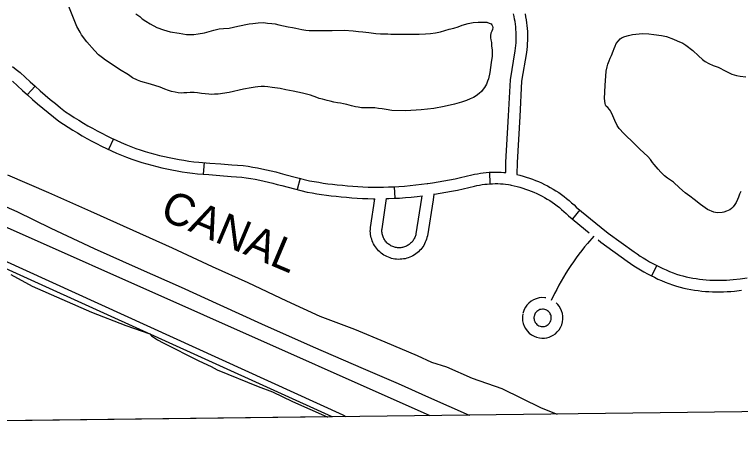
# Model space of a CAD drawing. Extents: x 3704301 to 3742427, y 506229 to 532009.
# Drawn here: x 3717011 to 3718892, y 511646 to 512803 of the extents above; entities that cross this region are included whole.
import ezdxf

# ---------------------------------------------------------------- set-up
doc = ezdxf.new("R2010")
doc.units = 0
for name, color, linetype in [('V-GRID-FRAM', 7, 'Continuous'), ('V-LEVE-TOET', 7, 'Continuous'), ('V-RIVR-IDEN', 7, 'Continuous'), ('V-ROAD-CNTR', 7, 'Continuous'), ('V-SITE-VEGE', 7, 'Continuous'), ('V-TOPO-BNDY', 7, 'Continuous'), ('V-TOPO-SHOR', 7, 'Continuous')]:
    doc.layers.add(name, color=color, linetype=linetype)

msp = doc.modelspace()

# ---------------------------------------------------------------- linework, layer by layer
at = {"layer": 'V-GRID-FRAM'}
msp.add_lwpolyline([(3708355.7, 529827.8), (3740022.4, 530214.7), (3740252.5, 512033.3), (3708569.9, 511646.2), (3708355.7, 529827.8)], dxfattribs=at)
at = {"layer": 'V-LEVE-TOET'}
for points in [[(3715612.8, 512669.7), (3716188.4, 512588.5), (3716253.4, 512575), (3716326.9, 512545.9), (3718086.8, 511762.5)], [(3717870.2, 511759.8), (3717862.2, 511763.5), (3716347.2, 512454.4), (3716290.4, 512479.5), (3716249.5, 512494.5), (3716192.9, 512507.2), (3715594.6, 512592.7)]]:
    msp.add_lwpolyline(points, dxfattribs=at)
at = {"layer": 'V-ROAD-CNTR'}
for p, q in [((3717063.9, 512616.6), (3717043.8, 512594.3)), ((3717266.8, 512480.2), (3717254.1, 512453)), ((3717502.1, 512418.5), (3717499.7, 512388.6)), ((3718241, 512393.6), (3718242.5, 512363.6)), ((3717750.5, 512378), (3717743.2, 512348.9)), ((3717994.2, 512356), (3717995.8, 512326)), ((3718475, 512296), (3718456, 512272.8)), ((3718674.5, 512151.8), (3718661.1, 512124.9))]:
    msp.add_line(p, q, dxfattribs=at)
for points in [[(3718283.3, 512392.8), (3718284.1, 512420.2), (3718291, 512539.7), (3718295.6, 512633.4), (3718308, 512708.8), (3718309, 512715.7), (3718309.7, 512722.5), (3718310.2, 512729.4), (3718310.6, 512736.2), (3718310.8, 512743.1), (3718310.7, 512750), (3718310.5, 512756.9), (3718310, 512763.7), (3718309.4, 512770.6), (3718308.6, 512777.4), (3718307.6, 512784.2), (3718306.4, 512791), (3718305, 512797.8), (3718303.4, 512804.5)], [(3718313.1, 512387.5), (3718314.1, 512418.9), (3718320.9, 512538.1), (3718325.5, 512630.2), (3718337.7, 512704.3), (3718338.7, 512712), (3718339.6, 512719.7), (3718340.2, 512727.4), (3718340.6, 512735.1), (3718340.8, 512742.9), (3718340.7, 512750.6), (3718340.4, 512758.3), (3718340, 512766.1), (3718339.2, 512773.8), (3718338.3, 512781.4), (3718337.2, 512789.1), (3718335.8, 512796.7), (3718334.2, 512804.3)], [(3717005.2, 512667.8), (3717015.2, 512660.3), (3717025.5, 512652.2), (3717038.6, 512639.8), (3717051.2, 512628.1), (3717064, 512616.5), (3717076.9, 512605.1), (3717090, 512593.8), (3717103.2, 512582.7), (3717116.5, 512571.8), (3717129.9, 512561), (3717143.1, 512550.7), (3717154.2, 512543.2), (3717165.7, 512535.8), (3717177.4, 512528.4), (3717189.1, 512521.3), (3717201, 512514.4), (3717213, 512507.6), (3717225, 512501), (3717237.2, 512494.6), (3717249.5, 512488.5), (3717261.9, 512482.4), (3717274.3, 512476.6), (3717286.9, 512471), (3717299.5, 512465.6), (3717312.2, 512460.4), (3717324.7, 512455.5), (3717336.7, 512451.5), (3717349.1, 512447.7), (3717361.5, 512444), (3717373.9, 512440.6), (3717386.5, 512437.4), (3717399, 512434.4), (3717411.6, 512431.7), (3717424.3, 512429.1), (3717437, 512426.8), (3717449.8, 512424.6), (3717462.5, 512422.7), (3717475.4, 512421), (3717488.1, 512419.6), (3717516.5, 512417.3), (3717545.3, 512415.1), (3717574, 512412.9), (3717603.3, 512410.8), (3717615.8, 512409), (3717627.8, 512407.1), (3717639.9, 512404.9), (3717651.9, 512402.6), (3717663.8, 512400.1), (3717675.7, 512397.3), (3717687.6, 512394.4), (3717699.4, 512391.3), (3717710.8, 512388), (3717775.4, 512371.7), (3717787, 512369.5), (3717799, 512367.5)], [(3717005.9, 512629.4), (3717018.1, 512617.9), (3717031, 512605.9), (3717044, 512594.1), (3717057.2, 512582.5), (3717070.5, 512571), (3717084, 512559.7), (3717097.6, 512548.5), (3717111.3, 512537.5), (3717125.5, 512526.4), (3717137.6, 512518.2), (3717149.6, 512510.5), (3717161.6, 512502.9), (3717173.8, 512495.5), (3717186, 512488.4), (3717198.4, 512481.4), (3717210.9, 512474.6), (3717223.5, 512468), (3717236.2, 512461.6), (3717249, 512455.4), (3717261.8, 512449.3), (3717274.8, 512443.5), (3717287.9, 512437.9), (3717301, 512432.5), (3717314.5, 512427.2), (3717327.6, 512422.9), (3717340.4, 512418.9), (3717353.3, 512415.2), (3717366.3, 512411.6), (3717379.3, 512408.3), (3717392.3, 512405.2), (3717405.5, 512402.3), (3717418.6, 512399.7), (3717431.8, 512397.2), (3717445.1, 512395), (3717458.4, 512393), (3717471.7, 512391.3), (3717485.2, 512389.7), (3717514.2, 512387.4), (3717543, 512385.2), (3717571.8, 512383), (3717600.1, 512380.9), (3717611.3, 512379.3), (3717622.8, 512377.5), (3717634.4, 512375.4), (3717645.9, 512373.2), (3717657.3, 512370.8), (3717668.8, 512368.2), (3717680.1, 512365.3), (3717691.4, 512362.3), (3717703, 512359), (3717769, 512342.4), (3717781.7, 512340), (3717794, 512337.9)], [(3717798.8, 512367.5), (3717810.8, 512365.6), (3717822.8, 512364), (3717834.8, 512362.6), (3717847, 512361.4), (3717860.5, 512359.9), (3717873.7, 512358.5), (3717886.9, 512357.4), (3717900.2, 512356.5), (3717913.5, 512355.8), (3717926.8, 512355.3), (3717940.1, 512355), (3717953.4, 512354.9), (3717961.2, 512355), (3717966.7, 512355.1), (3717979.9, 512355.4), (3717993.2, 512355.9), (3718006.5, 512356.7), (3718021.1, 512357.8), (3718035.7, 512359.1), (3718050.3, 512360.6), (3718065, 512362.4), (3718079.5, 512364.3), (3718081.2, 512364.5), (3718094.1, 512366.4), (3718108.6, 512368.7), (3718123.1, 512371.3), (3718137.6, 512374), (3718152, 512376.9), (3718166.4, 512380), (3718180.7, 512383.3), (3718195.3, 512386.8), (3718202.7, 512388.5), (3718210.2, 512389.9), (3718217.7, 512391.2), (3718225.3, 512392.2), (3718232.9, 512393), (3718240.6, 512393.6), (3718248.2, 512394), (3718255.9, 512394.1), (3718263.5, 512394.1), (3718271.2, 512393.8), (3718278.8, 512393.3), (3718283.5, 512392.8)], [(3718312.5, 512387.7), (3718320.3, 512385.8), (3718328.5, 512383.6), (3718336.7, 512381.2), (3718344.7, 512378.5), (3718352.7, 512375.7), (3718360.7, 512372.6), (3718368.5, 512369.3), (3718376.3, 512365.8), (3718383.9, 512362.1), (3718391.5, 512358.2), (3718398.9, 512354.1), (3718406.3, 512349.8), (3718413.5, 512345.3), (3718420.6, 512340.7), (3718427.6, 512335.8), (3718434.4, 512330.7), (3718441.1, 512325.5), (3718447.7, 512320.1), (3718454.1, 512314.5), (3718460.4, 512308.8), (3718465.9, 512303.5), (3718530.8, 512250.4), (3718548.4, 512236), (3718615.8, 512187.3), (3718623.7, 512181.7), (3718631.7, 512176.4), (3718639.7, 512171.3), (3718647.9, 512166.3), (3718656.2, 512161.5), (3718664.6, 512156.9), (3718673.1, 512152.4), (3718681.7, 512148.2), (3718690.3, 512144.1), (3718699.1, 512140.2), (3718707.9, 512136.5), (3718716.8, 512133), (3718725.8, 512129.7), (3718734.5, 512126.7), (3718742.6, 512124.6), (3718751.1, 512122.5), (3718759.7, 512120.7), (3718768.3, 512119.1), (3718776.9, 512117.7), (3718785.6, 512116.5), (3718794.3, 512115.4), (3718803, 512114.6), (3718811.8, 512114), (3718820.5, 512113.6), (3718829.3, 512113.4), (3718838.1, 512113.4), (3718846.8, 512113.6), (3718855.6, 512114), (3718864.3, 512114.6), (3718873.1, 512115.4), (3718891.1, 512117.4), (3718909, 512119.6)], [(3718096.5, 512336.5), (3718098.6, 512336.8), (3718113.6, 512339.1), (3718128.5, 512341.7), (3718143.3, 512344.5), (3718158.1, 512347.5), (3718172.9, 512350.7), (3718187.7, 512354.1), (3718202.1, 512357.6), (3718208.8, 512359.1), (3718215.5, 512360.4), (3718222.2, 512361.5), (3718228.9, 512362.4), (3718235.7, 512363.1), (3718242.5, 512363.6), (3718249.2, 512364), (3718256, 512364.1), (3718262.8, 512364.1), (3718269.6, 512363.8), (3718276.4, 512363.4), (3718282.9, 512362.7), (3718290.3, 512361.6), (3718295, 512360.7), (3718297.8, 512360.2), (3718305.4, 512358.6), (3718312.9, 512356.8), (3718320.3, 512354.7), (3718327.7, 512352.5), (3718335, 512350.1), (3718342.3, 512347.5), (3718349.5, 512344.8), (3718356.6, 512341.8), (3718363.6, 512338.6), (3718370.5, 512335.3), (3718377.4, 512331.7), (3718384.1, 512328), (3718390.8, 512324.1), (3718397.3, 512320.1), (3718403.8, 512315.8), (3718410.1, 512311.4), (3718416.3, 512306.8), (3718422.4, 512302.1), (3718428.3, 512297.2), (3718434.1, 512292.2), (3718439.8, 512286.9), (3718445.9, 512281), (3718499.9, 512236.9)], [(3717794.2, 512337.8), (3717806.5, 512336), (3717819, 512334.3), (3717831.5, 512332.8), (3717843.8, 512331.6), (3717857.3, 512330), (3717871, 512328.7), (3717884.7, 512327.5), (3717898.4, 512326.6), (3717912.1, 512325.8), (3717925.9, 512325.3), (3717939.6, 512325), (3717944, 512325)], [(3718096.9, 512336.5), (3718095.2, 512322.5), (3718080.3, 512228.6), (3718079.4, 512224.3), (3718078.2, 512220.1), (3718076.8, 512216), (3718075.1, 512211.9), (3718073.2, 512208), (3718071.1, 512204.1), (3718068.7, 512200.4), (3718066.2, 512196.9), (3718063.4, 512193.5), (3718060.4, 512190.3), (3718057.3, 512187.2), (3718053.9, 512184.4), (3718050.4, 512181.7), (3718046.8, 512179.3), (3718043, 512177), (3718039.1, 512175), (3718035.1, 512173.3), (3718031, 512171.8), (3718026.8, 512170.5), (3718022.6, 512169.4), (3718018.3, 512168.7), (3718013.9, 512168.1), (3718009.5, 512167.9), (3718005.2, 512167.8), (3718000.8, 512168.1), (3717996.4, 512168.6), (3717992.1, 512169.3), (3717987.8, 512170.4), (3717983.6, 512171.6), (3717979.5, 512173.1), (3717975.5, 512174.9), (3717971.6, 512176.8), (3717967.8, 512179), (3717964.2, 512181.5), (3717960.6, 512184.1), (3717957.3, 512186.9), (3717954.1, 512189.9), (3717951.1, 512193.2), (3717948.4, 512196.5), (3717945.8, 512200.1), (3717943.4, 512203.7), (3717941.2, 512207.6), (3717939.3, 512211.5), (3717937.6, 512215.5), (3717936.1, 512219.7), (3717934.9, 512223.9), (3717934, 512228.2), (3717933.3, 512232.5), (3717932.8, 512236.8), (3717932.6, 512241.2), (3717932.7, 512245.6), (3717933, 512250.1), (3717944, 512325)], [(3718066.2, 512332.3), (3718065.5, 512326.6), (3718050.8, 512234.1), (3718050.3, 512231.6), (3718049.6, 512229), (3718048.7, 512226.6), (3718047.7, 512224.2), (3718046.6, 512221.8), (3718045.3, 512219.5), (3718043.9, 512217.3), (3718042.4, 512215.2), (3718040.7, 512213.2), (3718038.9, 512211.2), (3718037.1, 512209.4), (3718035.1, 512207.7), (3718033, 512206.1), (3718030.8, 512204.7), (3718028.6, 512203.3), (3718026.2, 512202.1), (3718023.8, 512201.1), (3718021.4, 512200.2), (3718018.9, 512199.4), (3718016.3, 512198.8), (3718013.8, 512198.3), (3718011.2, 512198), (3718008.6, 512197.9), (3718005.9, 512197.8), (3718003.3, 512198), (3718000.7, 512198.3), (3717998.2, 512198.7), (3717995.6, 512199.3), (3717993.1, 512200.1), (3717990.6, 512201), (3717988.2, 512202), (3717985.9, 512203.2), (3717983.6, 512204.5), (3717981.5, 512206), (3717979.4, 512207.5), (3717977.4, 512209.2), (3717975.5, 512211), (3717973.7, 512213), (3717972, 512215), (3717970.5, 512217.1), (3717969.1, 512219.3), (3717967.8, 512221.6), (3717966.6, 512223.9), (3717965.6, 512226.3), (3717964.7, 512228.8), (3717964, 512231.3), (3717963.4, 512233.9), (3717963, 512236.4), (3717962.8, 512239), (3717962.6, 512241.7), (3717962.7, 512244.3), (3717962.9, 512246.8), (3717974.4, 512325.2)], [(3717974.1, 512325.2), (3717980.9, 512325.4), (3717994.7, 512326), (3718008.4, 512326.7), (3718023.6, 512327.9), (3718038.6, 512329.3), (3718053.7, 512330.8), (3718066.5, 512332.3)], [(3718511.4, 512227.5), (3718495.3, 512209.2), (3718487.7, 512199.9), (3718480.2, 512190.5), (3718473, 512181), (3718465.9, 512171.4), (3718458.9, 512161.6), (3718452.2, 512151.7), (3718445.6, 512141.7), (3718439.2, 512131.6), (3718433, 512121.4), (3718426.9, 512111), (3718421.1, 512100.6), (3718415.4, 512090), (3718409.9, 512079.4), (3718400.8, 512060.8)], [(3718522.8, 512218.1), (3718530.1, 512212.2), (3718598.4, 512162.8), (3718606.8, 512157), (3718615.3, 512151.3), (3718623.9, 512145.8), (3718632.6, 512140.5), (3718641.5, 512135.4), (3718650.4, 512130.5), (3718659.5, 512125.7), (3718668.6, 512121.2), (3718677.9, 512116.8), (3718687.2, 512112.7), (3718696.6, 512108.7), (3718706.1, 512105), (3718715.7, 512101.4), (3718725.8, 512097.9), (3718735.3, 512095.5), (3718744.5, 512093.3), (3718753.8, 512091.3), (3718763.1, 512089.6), (3718772.4, 512088), (3718781.8, 512086.7), (3718791.2, 512085.6), (3718800.6, 512084.7), (3718810, 512084.1), (3718819.5, 512083.6), (3718828.9, 512083.4), (3718838.4, 512083.4), (3718847.9, 512083.6), (3718857.3, 512084), (3718866.7, 512084.7), (3718876.1, 512085.6), (3718894.6, 512087.6)], [(3718327.5, 512025.7), (3718326.7, 512020.7), (3718326.5, 512014.5), (3718327.1, 512008), (3718328.6, 512001.3), (3718331, 511994.6), (3718334.5, 511988.1), (3718338.9, 511982.1), (3718344.2, 511976.7), (3718350.2, 511972.1), (3718356.7, 511968.4), (3718363.5, 511965.8), (3718370.5, 511964.1), (3718377.3, 511963.5), (3718383.8, 511963.6), (3718390, 511964.6), (3718395.6, 511966.1), (3718401.1, 511968.3), (3718406.6, 511971.2), (3718412, 511975), (3718417, 511979.6), (3718421.6, 511985.1), (3718425.5, 511991.3), (3718428.5, 511998.1), (3718430.5, 512005.4), (3718431.5, 512012.9), (3718431.4, 512020.4), (3718430.3, 512027.6), (3718428.2, 512034.5), (3718425.4, 512040.7), (3718422, 512046.3), (3718418.1, 512051.1), (3718413.9, 512055.3)], [(3718387.3, 512067.8), (3718384.6, 512068.2), (3718377.2, 512068.5), (3718369.8, 512067.7), (3718362.5, 512065.8), (3718355.5, 512062.9), (3718349, 512059.1), (3718343.3, 512054.5), (3718338.4, 512049.3), (3718334.5, 512043.8), (3718331.3, 512038), (3718329.1, 512032.2), (3718327.8, 512027.3)], [(3718357.1, 512021.3), (3718356.6, 512018), (3718356.6, 512015.4), (3718356.8, 512012.6), (3718357.5, 512009.7), (3718358.5, 512006.8), (3718360, 512004.1), (3718361.9, 512001.5), (3718364.1, 511999.2), (3718366.7, 511997.2), (3718369.5, 511995.6), (3718372.4, 511994.5), (3718375.4, 511993.8), (3718378.3, 511993.5), (3718381.1, 511993.6), (3718383.8, 511994), (3718386.2, 511994.6), (3718388.5, 511995.5), (3718390.8, 511996.8), (3718393.1, 511998.4), (3718395.3, 512000.4), (3718397.2, 512002.7), (3718398.9, 512005.4), (3718400.2, 512008.3), (3718401.1, 512011.5), (3718401.5, 512014.7), (3718401.5, 512017.9), (3718401, 512021), (3718400.1, 512023.9), (3718398.9, 512026.6), (3718397.4, 512029), (3718395.8, 512031), (3718394, 512032.8), (3718392, 512034.3), (3718389.8, 512035.8), (3718389.5, 512035.9), (3718387.2, 512036.9), (3718384.4, 512037.8), (3718381.4, 512038.3), (3718378.3, 512038.4), (3718375.1, 512038.1), (3718372, 512037.3), (3718369, 512036.1), (3718366.2, 512034.4), (3718363.8, 512032.5), (3718361.7, 512030.2), (3718359.9, 512027.8), (3718358.6, 512025.4), (3718357.6, 512022.9), (3718356.8, 512019.7)]]:
    msp.add_lwpolyline(points, dxfattribs=at)
at = {"layer": 'V-SITE-VEGE'}
for p, q in [((3717001.6, 512128.3), (3717056.4, 512097.9)), ((3717056.4, 512097.9), (3717209.9, 512030.5)), ((3717209.9, 512030.5), (3717299.2, 511996.5)), ((3717299.2, 511996.5), (3717361.2, 511974.5)), ((3717361.2, 511974.5), (3717365.5, 511969.4)), ((3717365.5, 511969.4), (3717381.3, 511959.2)), ((3717381.3, 511959.2), (3717396.1, 511951.1)), ((3717396.1, 511951.1), (3717488.7, 511904.6)), ((3717488.7, 511904.6), (3717520.3, 511889.5)), ((3717520.3, 511889.5), (3717536.1, 511881.4)), ((3717536.1, 511881.4), (3717642.2, 511838.3)), ((3717642.2, 511838.3), (3717679, 511824.3)), ((3717679, 511824.3), (3717730.6, 511799)), ((3717730.6, 511799), (3717821, 511759.8)), ((3717822.3, 511759.2), (3713375.9, 511704.9)), ((3717821, 511759.8), (3717822.3, 511759.2))]:
    msp.add_line(p, q, dxfattribs=at)
at = {"layer": 'V-TOPO-BNDY'}
msp.add_lwpolyline([(3717833.4, 511759.4), (3716282.7, 512464.2), (3712071, 513015.8), (3710790.9, 512288), (3709881.7, 512419.6), (3709491.4, 512595.4), (3708839.8, 512879.9), (3708554.4, 512966.9)], dxfattribs=at)
at = {"layer": 'V-TOPO-SHOR'}
for points in [[(3717306.4, 512646.2), (3717283.1, 512660.1), (3717261.2, 512675), (3717246.1, 512684.4), (3717238.5, 512690), (3717228.7, 512698.4), (3717218.2, 512709.3), (3717198.4, 512731.8), (3717184.7, 512750.3), (3717181, 512756.5), (3717172, 512771.4), (3717163.2, 512793.4), (3717151.5, 512823.2)], [(3717325.3, 512804.8), (3717335.2, 512797.4), (3717341.5, 512791.8), (3717350.7, 512785.2), (3717362.4, 512778.5), (3717379.1, 512769), (3717396.6, 512763), (3717414.4, 512758.1), (3717437.6, 512754.2), (3717456.1, 512750.5), (3717475.4, 512750.7), (3717486.5, 512752.5), (3717502.6, 512755.4), (3717526.9, 512762.4), (3717540.9, 512765.6), (3717552, 512766.8), (3717566.9, 512767.4), (3717589.4, 512772.4), (3717618.9, 512778.2), (3717627.9, 512779.6), (3717642.1, 512781.2), (3717655.7, 512781.6), (3717666.5, 512780.5), (3717677.4, 512779.6), (3717686.2, 512778.3), (3717695.9, 512776), (3717707.4, 512773.5), (3717720.1, 512770.8), (3717730.8, 512768.9), (3717739.2, 512767.4), (3717747, 512765.9), (3717755.3, 512764.1), (3717765.1, 512762), (3717774.1, 512760.9), (3717787.7, 512760.8), (3717833.6, 512761.1), (3717864.4, 512762), (3717888.1, 512760.5), (3717901.7, 512758.9), (3717913.6, 512757.4), (3717928.6, 512755.6), (3717946.6, 512753.6), (3717959.3, 512752.7), (3717968.4, 512752.3), (3717977.9, 512752.2), (3717985.9, 512751.5), (3718008.9, 512751.7), (3718022, 512751.6), (3718059.2, 512751.4), (3718075.8, 512752.7), (3718088.6, 512753.6), (3718101.5, 512755.2), (3718114.6, 512757.8), (3718125.6, 512760.9), (3718136.9, 512764.3), (3718149, 512767.6), (3718160.3, 512770.7)], [(3718160.3, 512770.7), (3718170.7, 512774.9), (3718186.1, 512779.6), (3718198.9, 512781.7), (3718211.9, 512782.4), (3718223.8, 512783.1), (3718230.5, 512782.9), (3718234.5, 512782.4), (3718240.4, 512780.6), (3718245.3, 512778.6), (3718247.3, 512776.1), (3718248.8, 512772.1), (3718249.7, 512768.9), (3718249.4, 512763.7), (3718247.7, 512759.6), (3718245.1, 512754.3), (3718243.7, 512748.1), (3718244.2, 512742), (3718245.2, 512736.9), (3718246.2, 512729.7), (3718246.9, 512721.4), (3718248.6, 512710.6), (3718248.4, 512694.7), (3718245.5, 512678.1), (3718242.1, 512651.9), (3718238.5, 512636.1), (3718236.5, 512629.4), (3718233.5, 512622.4), (3718228.8, 512613.8), (3718225.2, 512608.7), (3718220.3, 512602.9), (3718214.4, 512598), (3718206.5, 512591.8), (3718199.5, 512587.6), (3718191.1, 512584), (3718181.6, 512580), (3718169.1, 512575.3), (3718150.4, 512570.3), (3718123.7, 512564.2), (3718096.7, 512558.8), (3718064, 512555.4), (3718024.8, 512553), (3717988.5, 512553.7), (3717974, 512556), (3717963.1, 512557.7), (3717953.5, 512558.8), (3717944.1, 512560.3), (3717933.6, 512560.6), (3717924, 512560.7), (3717910.1, 512560.6), (3717901.3, 512562.4), (3717894.6, 512563), (3717890.4, 512563.9), (3717884, 512565.8), (3717872, 512569.2), (3717863.1, 512570.9), (3717855.1, 512572.4), (3717847.7, 512573.9), (3717838.4, 512575.7), (3717828.6, 512577.8), (3717820.5, 512580.1), (3717808.9, 512582.9), (3717799.9, 512585), (3717793.7, 512587.4), (3717777.6, 512593.4), (3717756.7, 512599.1), (3717732.8, 512603.6), (3717713.7, 512607.6), (3717699.2, 512610.4), (3717678, 512613.6), (3717666.8, 512615.3), (3717658.3, 512616.2), (3717649.8, 512616.1), (3717641.2, 512615.5), (3717634, 512614.4), (3717623.6, 512612.5), (3717603.6, 512609.2), (3717566.6, 512600.5), (3717538, 512596.3), (3717529.2, 512595.7), (3717521.5, 512595.6), (3717514.1, 512596.4), (3717504.5, 512597.1), (3717495.2, 512598.2), (3717485, 512599.4), (3717475.9, 512600.3), (3717465.8, 512600.2), (3717457.5, 512599.5), (3717449.8, 512599.2), (3717442.5, 512599.1), (3717434.9, 512599.8), (3717427.1, 512601.4), (3717417.3, 512603.1), (3717409.4, 512605.7), (3717400.4, 512609.3), (3717387.7, 512614.4), (3717362.7, 512622), (3717337.6, 512628.8), (3717329.2, 512632.1), (3717316.6, 512638.8), (3717306.4, 512646.2)], [(3718548.3, 512674.2), (3718551.5, 512682.2), (3718554, 512689.1), (3718557.1, 512696.4), (3718561.8, 512707.2), (3718564.5, 512714.6), (3718566.8, 512720.9), (3718569.9, 512727.2), (3718575.5, 512734.8), (3718580.3, 512739.7), (3718585.2, 512743.1), (3718592.2, 512745.9), (3718601.7, 512748.6), (3718611.6, 512750.6), (3718620.9, 512752.1), (3718637.5, 512753.5), (3718653.9, 512752.4), (3718666.7, 512751.1), (3718687.3, 512748.3), (3718700.3, 512745.7), (3718718.4, 512739), (3718727.5, 512734.1), (3718742, 512728.2), (3718749.8, 512723.4), (3718768.1, 512709.1), (3718782.7, 512695.1), (3718793.4, 512685.7), (3718800.4, 512680.7), (3718810, 512676), (3718820.6, 512670.8), (3718833.6, 512665.8), (3718853.9, 512655.8), (3718869.2, 512648), (3718881, 512644.4), (3718890.9, 512642.9), (3718905.9, 512641.2)], [(3718892.4, 512343.8), (3718889.5, 512336.8), (3718886.4, 512329.3), (3718883.9, 512322.9), (3718880.4, 512315.5), (3718877.1, 512309.6), (3718872.7, 512303.8), (3718868.1, 512299.4), (3718863.9, 512296.1), (3718855.8, 512292.5), (3718848.3, 512290.1), (3718843.9, 512289.2), (3718831.1, 512288.5), (3718822.3, 512289.7), (3718806.4, 512296.7), (3718787.8, 512310.2), (3718771.3, 512323.2), (3718760, 512331.5), (3718748.2, 512340.6), (3718733.9, 512353.6), (3718718.4, 512367.5), (3718702.6, 512378.2), (3718694.6, 512384), (3718685.5, 512393.6), (3718678.3, 512401.6), (3718673.1, 512407.8), (3718668.4, 512413.8), (3718664, 512419.3), (3718658.2, 512427.1), (3718651.6, 512434.4), (3718641.2, 512444.2), (3718631.2, 512453.9), (3718616.7, 512467.2), (3718589.8, 512494.4), (3718577.7, 512506.8), (3718572, 512514.9), (3718566, 512527.8), (3718560.9, 512540.2), (3718556.6, 512549.1), (3718554.5, 512552.9), (3718552.1, 512556.5), (3718548.2, 512561.4), (3718544.4, 512564.3), (3718542.5, 512566), (3718541.9, 512568.3), (3718541.3, 512571.7), (3718539.6, 512584.7), (3718540.9, 512619), (3718543.4, 512655.6), (3718545.8, 512667), (3718548.3, 512674.2)], [(3716992.9, 512386.6), (3717098.7, 512341.4), (3717207.9, 512292.9), (3717317.5, 512243.5), (3717419.2, 512197.7), (3717522.9, 512148.9), (3717615.2, 512107.6), (3717715.2, 512060.6), (3717802, 512020.4), (3717891.4, 511986.4), (3717970.1, 511953.5), (3718054.1, 511918.3), (3718091, 511901.5), (3718129.8, 511889.3), (3718196.8, 511860), (3718273.1, 511832.5), (3718375, 511783), (3718416.3, 511766.5)], [(3716917.6, 512335.5), (3717016.4, 512291.9), (3717104.4, 512248.3), (3717217, 512196.2), (3717331, 512145), (3717442.2, 512095.4), (3717542.8, 512049.5), (3717651, 512000.6), (3717784.5, 511940.8), (3717913.7, 511884.9), (3718004.8, 511845.5), (3718082.9, 511810.6), (3718188.8, 511764.1), (3718189.7, 511763.7)]]:
    msp.add_lwpolyline(points, dxfattribs=at)

# ---------------------------------------------------------------- texts
at = {"layer": 'V-RIVR-IDEN'}
msp.add_text('CANAL', height=83, rotation=337.2079, dxfattribs=at).set_placement((3717384.1, 512274.1))

doc.saveas('drawing.dxf')
